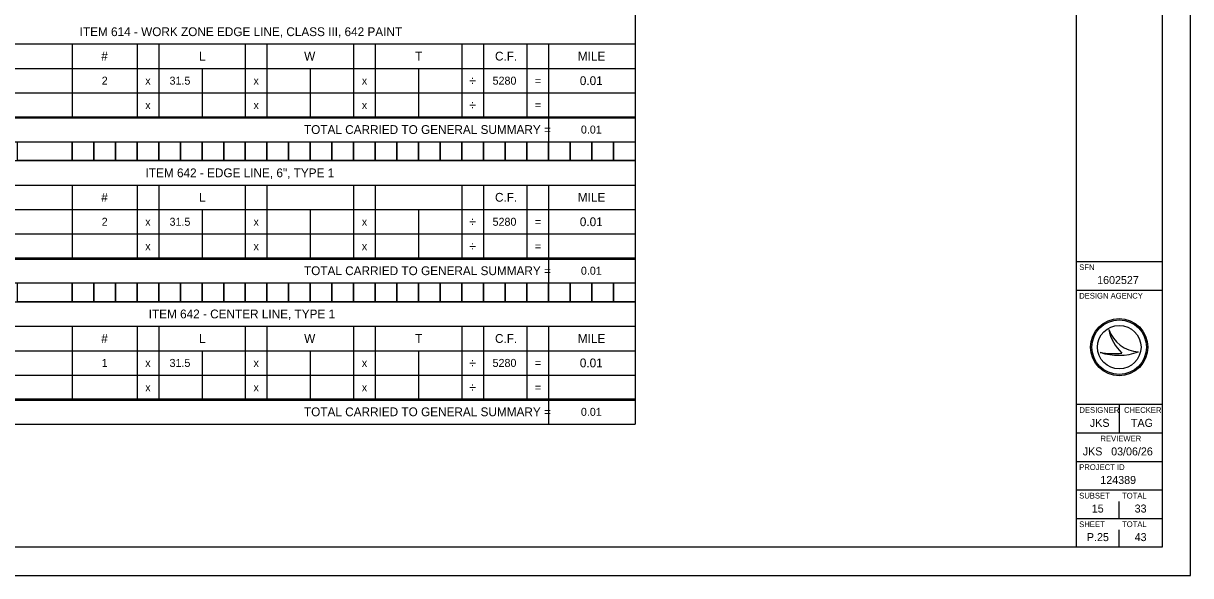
# Model space of a CAD drawing. Extents: x 0 to 34, y 0 to 22.
# Drawn here: x 13.58 to 34, y 0 to 9.67 of the extents above; entities that cross this region are included whole.
import ezdxf

# ---------------------------------------------------------------- set-up
doc = ezdxf.new("R2010")
doc.units = 0
for name, color, linetype in [('Default', 7, 'Continuous'), ('SH_Border', 7, 'Continuous'), ('SH_Cut_Line', 7, 'Continuous'), ('SH_Data', 7, 'Continuous')]:
    doc.layers.add(name, color=color, linetype=linetype)

msp = doc.modelspace()

# ---------------------------------------------------------------- linework, layer by layer
at = {"layer": 'Default'}
for p, q in [((24.279, 10.505), (24.279, 8.012)), ((10.444, 9.308), (24.279, 9.308)), ((14.43, 9.308), (14.43, 8.034)), ((15.566, 9.308), (15.566, 8.034)), ((15.945, 9.308), (15.945, 8.034)), ((17.46, 9.308), (17.46, 8.034)), ((17.839, 9.308), (17.839, 8.034)), ((19.355, 9.308), (19.355, 8.034)), ((19.733, 9.308), (19.733, 8.034)), ((21.249, 9.308), (21.249, 8.034)), ((21.628, 9.308), (21.628, 8.034)), ((22.385, 9.308), (22.385, 8.034)), ((22.764, 9.308), (22.764, 8.034)), ((10.444, 8.88), (24.279, 8.88)), ((16.703, 8.88), (16.703, 8.034)), ((18.597, 8.88), (18.597, 8.034)), ((20.491, 8.88), (20.491, 8.034)), ((10.444, 8.451), (24.279, 8.451)), ((10.444, 8.034), (24.279, 8.034)), ((10.444, 8.012), (24.279, 8.012)), ((22.764, 8.012), (22.764, 7.595)), ((24.279, 8.034), (24.279, 5.541)), ((10.444, 7.595), (24.279, 7.595)), ((10.444, 7.265), (24.279, 7.265)), ((10.444, 6.837), (24.279, 6.837)), ((14.43, 6.837), (14.43, 5.563)), ((15.566, 6.837), (15.566, 5.563)), ((15.945, 6.837), (15.945, 5.563)), ((17.46, 6.837), (17.46, 5.563)), ((17.839, 6.837), (17.839, 5.563)), ((19.355, 6.837), (19.355, 5.563)), ((19.733, 6.837), (19.733, 5.563)), ((21.249, 6.837), (21.249, 5.563)), ((21.628, 6.837), (21.628, 5.563)), ((22.385, 6.837), (22.385, 5.563)), ((22.764, 6.837), (22.764, 5.563)), ((10.444, 6.409), (24.279, 6.409)), ((16.703, 6.409), (16.703, 5.563)), ((18.597, 6.409), (18.597, 5.563)), ((20.491, 6.409), (20.491, 5.563)), ((10.444, 5.981), (24.279, 5.981)), ((10.444, 5.563), (24.279, 5.563)), ((10.444, 5.541), (24.279, 5.541)), ((22.764, 5.541), (22.764, 5.124)), ((24.279, 5.563), (24.279, 3.071)), ((10.444, 5.124), (24.279, 5.124)), ((10.444, 4.795), (24.279, 4.795)), ((10.444, 4.367), (24.279, 4.367)), ((14.43, 4.367), (14.43, 3.093)), ((15.566, 4.367), (15.566, 3.093)), ((15.945, 4.367), (15.945, 3.093)), ((17.46, 4.367), (17.46, 3.093)), ((17.839, 4.367), (17.839, 3.093)), ((19.355, 4.367), (19.355, 3.093)), ((19.733, 4.367), (19.733, 3.093)), ((21.249, 4.367), (21.249, 3.093)), ((21.628, 4.367), (21.628, 3.093)), ((22.385, 4.367), (22.385, 3.093)), ((22.764, 4.367), (22.764, 3.093)), ((10.444, 3.938), (24.279, 3.938)), ((16.703, 3.938), (16.703, 3.093)), ((18.597, 3.938), (18.597, 3.093)), ((20.491, 3.938), (20.491, 3.093)), ((10.444, 3.51), (24.279, 3.51)), ((10.444, 3.093), (24.279, 3.093)), ((10.444, 3.071), (24.279, 3.071)), ((22.764, 3.071), (22.764, 2.654)), ((24.279, 3.093), (24.279, 2.654)), ((10.444, 2.654), (24.279, 2.654))]:
    msp.add_line(p, q, dxfattribs=at)
for points in [[(13.475, 7.595), (14.43, 7.595), (14.43, 7.265), (13.475, 7.265)], [(14.43, 7.595), (14.809, 7.595), (14.809, 7.265), (14.43, 7.265)], [(14.809, 7.595), (15.188, 7.595), (15.188, 7.265), (14.809, 7.265)], [(15.188, 7.595), (15.566, 7.595), (15.566, 7.265), (15.188, 7.265)], [(15.566, 7.595), (15.945, 7.595), (15.945, 7.265), (15.566, 7.265)], [(15.945, 7.595), (16.324, 7.595), (16.324, 7.265), (15.945, 7.265)], [(16.324, 7.595), (16.703, 7.595), (16.703, 7.265), (16.324, 7.265)], [(16.703, 7.595), (17.082, 7.595), (17.082, 7.265), (16.703, 7.265)], [(17.082, 7.595), (17.46, 7.595), (17.46, 7.265), (17.082, 7.265)], [(17.46, 7.595), (17.839, 7.595), (17.839, 7.265), (17.46, 7.265)], [(17.839, 7.595), (18.218, 7.595), (18.218, 7.265), (17.839, 7.265)], [(18.218, 7.595), (18.597, 7.595), (18.597, 7.265), (18.218, 7.265)], [(18.597, 7.595), (18.976, 7.595), (18.976, 7.265), (18.597, 7.265)], [(18.976, 7.595), (19.355, 7.595), (19.355, 7.265), (18.976, 7.265)], [(19.355, 7.595), (19.733, 7.595), (19.733, 7.265), (19.355, 7.265)], [(19.733, 7.595), (20.112, 7.595), (20.112, 7.265), (19.733, 7.265)], [(20.112, 7.595), (20.491, 7.595), (20.491, 7.265), (20.112, 7.265)], [(20.491, 7.595), (20.87, 7.595), (20.87, 7.265), (20.491, 7.265)], [(20.87, 7.595), (21.249, 7.595), (21.249, 7.265), (20.87, 7.265)], [(21.249, 7.595), (21.628, 7.595), (21.628, 7.265), (21.249, 7.265)], [(21.628, 7.595), (22.006, 7.595), (22.006, 7.265), (21.628, 7.265)], [(22.006, 7.595), (22.385, 7.595), (22.385, 7.265), (22.006, 7.265)], [(22.385, 7.595), (22.764, 7.595), (22.764, 7.265), (22.385, 7.265)], [(22.764, 7.595), (23.143, 7.595), (23.143, 7.265), (22.764, 7.265)], [(23.143, 7.595), (23.522, 7.595), (23.522, 7.265), (23.143, 7.265)], [(23.522, 7.595), (23.9, 7.595), (23.9, 7.265), (23.522, 7.265)], [(23.9, 7.595), (24.279, 7.595), (24.279, 7.265), (23.9, 7.265)], [(13.475, 5.124), (14.43, 5.124), (14.43, 4.795), (13.475, 4.795)], [(14.43, 5.124), (14.809, 5.124), (14.809, 4.795), (14.43, 4.795)], [(14.809, 5.124), (15.188, 5.124), (15.188, 4.795), (14.809, 4.795)], [(15.188, 5.124), (15.566, 5.124), (15.566, 4.795), (15.188, 4.795)], [(15.566, 5.124), (15.945, 5.124), (15.945, 4.795), (15.566, 4.795)], [(15.945, 5.124), (16.324, 5.124), (16.324, 4.795), (15.945, 4.795)], [(16.324, 5.124), (16.703, 5.124), (16.703, 4.795), (16.324, 4.795)], [(16.703, 5.124), (17.082, 5.124), (17.082, 4.795), (16.703, 4.795)], [(17.082, 5.124), (17.46, 5.124), (17.46, 4.795), (17.082, 4.795)], [(17.46, 5.124), (17.839, 5.124), (17.839, 4.795), (17.46, 4.795)], [(17.839, 5.124), (18.218, 5.124), (18.218, 4.795), (17.839, 4.795)], [(18.218, 5.124), (18.597, 5.124), (18.597, 4.795), (18.218, 4.795)], [(18.597, 5.124), (18.976, 5.124), (18.976, 4.795), (18.597, 4.795)], [(18.976, 5.124), (19.355, 5.124), (19.355, 4.795), (18.976, 4.795)], [(19.355, 5.124), (19.733, 5.124), (19.733, 4.795), (19.355, 4.795)], [(19.733, 5.124), (20.112, 5.124), (20.112, 4.795), (19.733, 4.795)], [(20.112, 5.124), (20.491, 5.124), (20.491, 4.795), (20.112, 4.795)], [(20.491, 5.124), (20.87, 5.124), (20.87, 4.795), (20.491, 4.795)], [(20.87, 5.124), (21.249, 5.124), (21.249, 4.795), (20.87, 4.795)], [(21.249, 5.124), (21.628, 5.124), (21.628, 4.795), (21.249, 4.795)], [(21.628, 5.124), (22.006, 5.124), (22.006, 4.795), (21.628, 4.795)], [(22.006, 5.124), (22.385, 5.124), (22.385, 4.795), (22.006, 4.795)], [(22.385, 5.124), (22.764, 5.124), (22.764, 4.795), (22.385, 4.795)], [(22.764, 5.124), (23.143, 5.124), (23.143, 4.795), (22.764, 4.795)], [(23.143, 5.124), (23.522, 5.124), (23.522, 4.795), (23.143, 4.795)], [(23.522, 5.124), (23.9, 5.124), (23.9, 4.795), (23.522, 4.795)], [(23.9, 5.124), (24.279, 5.124), (24.279, 4.795), (23.9, 4.795)]]:
    msp.add_lwpolyline(points, close=True, dxfattribs=at)
at = {"layer": 'SH_Border'}
for p, q in [((32, 0.5), (32, 21.5)), ((32, 5.5), (33.5, 5.5)), ((32, 5), (33.5, 5)), ((32, 3), (33.5, 3)), ((32.75, 3), (32.75, 2.5)), ((32, 2.5), (33.5, 2.5)), ((32, 2), (33.5, 2)), ((32, 1.5), (33.5, 1.5)), ((32, 1), (33.5, 1))]:
    msp.add_line(p, q, dxfattribs=at)
msp.add_lwpolyline([(1.5, 21.5), (33.5, 21.5), (33.5, 0.5), (1.5, 0.5)], close=True, dxfattribs=at)
at = {"layer": 'SH_Cut_Line'}
msp.add_lwpolyline([(0, 0), (34, 0), (34, 22), (0, 22)], close=True, dxfattribs=at)
at = {"layer": 'SH_Data'}
for p, q in [((32.567, 4.31), (32.567, 4.31)), ((32.417, 3.91), (32.417, 3.91)), ((32.75, 4), (32.75, 4)), ((33.087, 3.919), (33.087, 3.919)), ((32.75, 1), (32.75, 1.3)), ((32.375, 0.675), (32.375, 0.675)), ((32.75, 0.5), (32.75, 0.8))]:
    msp.add_line(p, q, dxfattribs=at)
for radius in [0.5, 0.477, 0.477, 0.382]:
    msp.add_circle((32.75, 4), radius, dxfattribs=at)
for centre, radius, start, end in [((33.116, 4.498), 0.58, 198.9257, 198.9319), ((33.347, 4.47), 0.796, 191.6379, 191.6421), ((33.116, 4.498), 0.58, 198.9319, 267.1657), ((33.347, 4.47), 0.796, 191.6421, 226.0947), ((32.739, 4.87), 1.013, 251.4576, 290.0832), ((32.648, 5.154), 1.266, 259.4964, 259.4995), ((32.739, 4.87), 1.013, 251.4527, 251.4576), ((32.648, 5.154), 1.266, 259.4995, 276.6672)]:
    msp.add_arc(centre, radius, start, end, dxfattribs=at)

# ---------------------------------------------------------------- texts
at = {"layer": 'Default'}
for s, height, p in [('ITEM 614 - WORK ZONE EDGE LINE, CLASS III, 642 PAINT', 0.154, (14.562, 9.445)), ('#', 0.154, (14.939, 9.017)), ('L', 0.154, (16.652, 9.017)), ('W', 0.154, (18.49, 9.017)), ('T', 0.154, (20.432, 9.017)), ('C.F.', 0.154, (21.829, 9.017)), ('MILE', 0.154, (23.278, 9.017)), ('2', 0.14, (14.948, 8.595)), ('x', 0.14, (15.71, 8.595)), ('31.5', 0.14, (16.135, 8.595)), ('x', 0.14, (17.604, 8.595)), ('x', 0.14, (19.499, 8.595)), ('÷', 0.168, (21.376, 8.581)), ('5280', 0.14, (21.787, 8.595)), ('=', 0.14, (22.525, 8.595)), ('0.01', 0.154, (23.313, 8.588)), ('x', 0.14, (15.71, 8.167)), ('x', 0.14, (17.604, 8.167)), ('x', 0.14, (19.499, 8.167)), ('÷', 0.168, (21.376, 8.153)), ('=', 0.14, (22.525, 8.167)), ('TOTAL CARRIED TO GENERAL SUMMARY =', 0.154, (18.487, 7.732)), ('0.01', 0.14, (23.332, 7.739)), ('ITEM 642 - EDGE LINE, 6", TYPE 1', 0.154, (15.716, 6.974)), ('#', 0.154, (14.939, 6.546)), ('L', 0.154, (16.652, 6.546)), ('C.F.', 0.154, (21.829, 6.546)), ('MILE', 0.154, (23.278, 6.546)), ('2', 0.14, (14.948, 6.125)), ('x', 0.14, (15.71, 6.125)), ('31.5', 0.14, (16.135, 6.125)), ('x', 0.14, (17.604, 6.125)), ('x', 0.14, (19.499, 6.125)), ('÷', 0.168, (21.376, 6.111)), ('5280', 0.14, (21.787, 6.125)), ('=', 0.14, (22.525, 6.125)), ('0.01', 0.154, (23.313, 6.118)), ('x', 0.14, (15.71, 5.697)), ('x', 0.14, (17.604, 5.697)), ('x', 0.14, (19.499, 5.697)), ('÷', 0.168, (21.376, 5.683)), ('=', 0.14, (22.525, 5.697)), ('TOTAL CARRIED TO GENERAL SUMMARY =', 0.154, (18.487, 5.261)), ('0.01', 0.14, (23.332, 5.268)), ('ITEM 642 - CENTER LINE, TYPE 1', 0.154, (15.77, 4.504)), ('#', 0.154, (14.939, 4.075)), ('L', 0.154, (16.652, 4.075)), ('W', 0.154, (18.49, 4.075)), ('T', 0.154, (20.432, 4.075)), ('C.F.', 0.154, (21.829, 4.075)), ('MILE', 0.154, (23.278, 4.075)), ('1', 0.14, (14.948, 3.654)), ('x', 0.14, (15.71, 3.654)), ('31.5', 0.14, (16.135, 3.654)), ('x', 0.14, (17.604, 3.654)), ('x', 0.14, (19.499, 3.654)), ('÷', 0.168, (21.376, 3.64)), ('5280', 0.14, (21.787, 3.654)), ('=', 0.14, (22.525, 3.654)), ('0.01', 0.154, (23.313, 3.647)), ('x', 0.14, (15.71, 3.226)), ('x', 0.14, (17.604, 3.226)), ('x', 0.14, (19.499, 3.226)), ('÷', 0.168, (21.376, 3.212)), ('=', 0.14, (22.525, 3.226)), ('TOTAL CARRIED TO GENERAL SUMMARY =', 0.154, (18.487, 2.791)), ('0.01', 0.14, (23.332, 2.798))]:
    msp.add_text(s, height=height, dxfattribs=at).set_placement(p)
at = {"layer": 'SH_Data'}
for s, height, p in [('SFN', 0.1, (32.05, 5.35)), ('1602527', 0.14, (32.364, 5.105)), ('DESIGN AGENCY', 0.1, (32.05, 4.85)), ('DESIGNER', 0.1, (32.054, 2.85)), ('CHECKER', 0.1, (32.835, 2.85)), ('JKS', 0.14, (32.237, 2.605)), ('TAG', 0.14, (32.955, 2.605)), ('JKS', 0.14, (32.112, 2.105)), ('REVIEWER', 0.1, (32.422, 2.35)), ('03/06/26', 0.14, (32.609, 2.105)), ('PROJECT ID', 0.1, (32.05, 1.85)), ('124389', 0.14, (32.42, 1.605)), ('SUBSET', 0.1, (32.05, 1.35)), ('TOTAL', 0.1, (32.8, 1.35)), ('15', 0.14, (32.27, 1.105)), ('33', 0.14, (33.02, 1.105)), ('SHEET', 0.1, (32.05, 0.85)), ('TOTAL', 0.1, (32.8, 0.85)), ('P.25', 0.14, (32.185, 0.605)), ('43', 0.14, (33.02, 0.605))]:
    msp.add_text(s, height=height, dxfattribs=at).set_placement(p)

doc.saveas('drawing.dxf')
